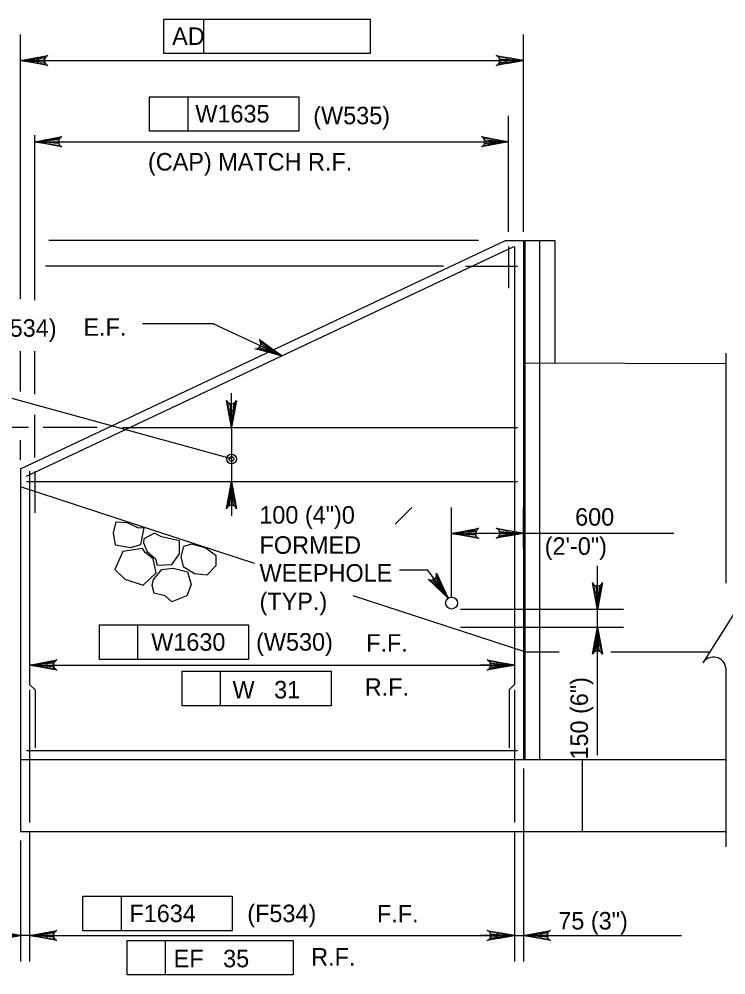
# Model space of a CAD drawing. Extents: x 634540 to 640306, y 296059 to 300275.
# Drawn here: x 639465.1 to 639586.1, y 297349.6 to 297513.4 of the extents above; entities that cross this region are included whole.
import ezdxf

# ---------------------------------------------------------------- set-up
doc = ezdxf.new("R2010")
doc.units = 0
for name, color, linetype in [('10', 7, 'Continuous'), ('3', 7, 'Continuous'), ('4', 7, 'Continuous'), ('5', 7, 'Continuous'), ('6', 7, 'Continuous')]:
    doc.layers.add(name, color=color, linetype=linetype)

# ---------------------------------------------------------------- blocks, each defined once
blk = doc.blocks.new('ROCK')
at = {"layer": '4'}
for points in [[(2.36725, 1.088), (2.2065, 0.82625), (2.378625, 0.506625), (2.66975, 0.3095), (3.128875, 0.403375), (3.48475, 0.6775), (3.4915, 1.123375), (3.25625, 1.36725), (2.783625, 1.308375)], [(1.10175, -0.02725), (1.4015, -0.159125), (1.78825, -0.148875), (1.980875, -0.266), (2.343375, 0.09475), (2.27875, 0.5505), (1.969375, 0.883), (1.4225, 0.553625), (1.152875, 0.479), (1.0105, 0.082)], [(0.74675, 0.359875), (0.882, 0.16), (1.072875, -0.144), (0.892, -0.457375), (0.448125, -0.758625), (0.1, -0.49325), (-0.095, -0.146375), (0.202875, 0.1025), (0.579125, 0.219875)], [(2.231375, -0.71725), (2.2025, -0.266375), (2.45475, 0.037125), (2.9085, 0.28875), (3.2995, 0.047625), (3.46875, -0.344), (3.231625, -0.855), (2.92, -0.860375), (2.5765, -1.054625), (2.340375, -0.904375)], [(1.2085, -0.192875), (0.778375, -0.737625), (1.008375, -1.391375), (1.48725, -1.396875), (2.09825, -1.106625), (2.133375, -0.486375), (1.723125, -0.203375), (1.37425, -0.239875)]]:
    blk.add_lwpolyline(points, close=True, dxfattribs=at)

msp = doc.modelspace()

# ---------------------------------------------------------------- linework, layer by layer
at = {"layer": '10'}
for p, q in [((639465.33, 297436.3), (639548.38, 297475.42)), ((639548.38, 297475.42), (639551.45, 297475.42)), ((639551.45, 297475.42), (639551.45, 297386.47)), ((639551.71, 297475.42), (639556.85, 297475.42)), ((639551.71, 297475.42), (639551.71, 297386.47)), ((639554.18, 297475.42), (639554.18, 297386.47)), ((639556.85, 297475.42), (639556.85, 297454.45)), ((639551.71, 297454.49), (639586.12, 297454.35)), ((639465.33, 297436.3), (639465.33, 297374.16)), ((639505.41, 297420.09), (639465.33, 297433.22)), ((639551.71, 297404.92), (639522.29, 297414.56)), ((639551.71, 297404.92), (639557.55, 297404.92)), ((639566.41, 297404.92), (639583.37, 297404.92)), ((639465.33, 297386.47), (639586.12, 297386.47)), ((639561.51, 297386.47), (639561.51, 297374.16)), ((639465.33, 297374.16), (639586.12, 297374.16))]:
    msp.add_line(p, q, dxfattribs=at)
at = {"layer": '3'}
for p, q in [((639586.12, 297456.16), (639586.12, 297416.69)), ((639590.1, 297415.62), (639582.19, 297403.05)), ((639586.12, 297402.12), (639586.12, 297371.54))]:
    msp.add_line(p, q, dxfattribs=at)
for radius in [0.833, 0.417]:
    msp.add_circle((639501.45, 297438.01), radius, dxfattribs=at)
msp.add_arc((639584, 297401.92), 2.13, 5.3286, 147.8672, dxfattribs=at)
at = {"layer": '4'}
for p, q in [((639489.87, 297513.39), (639525.17, 297513.39)), ((639489.87, 297507.49), (639489.87, 297513.39)), ((639496.71, 297507.49), (639496.71, 297513.39)), ((639525.17, 297513.39), (639525.17, 297507.49)), ((639465.33, 297465.44), (639465.33, 297510.73)), ((639551.45, 297476.96), (639551.45, 297510.73)), ((639525.17, 297507.49), (639489.87, 297507.49)), ((639468.28, 297506.3), (639548.5, 297506.3)), ((639487.42, 297500.1), (639512.96, 297500.1)), ((639487.42, 297494.2), (639487.42, 297500.1)), ((639494.01, 297494.2), (639494.01, 297500.1)), ((639512.96, 297500.1), (639512.96, 297494.2)), ((639548.9, 297476.96), (639548.9, 297496.8)), ((639512.96, 297494.2), (639487.42, 297494.2)), ((639467.75, 297465.24), (639467.75, 297493.53)), ((639467.75, 297492.37), (639548.9, 297492.37)), ((639543.78, 297475.42), (639470.18, 297475.42)), ((639537.78, 297471.06), (639469.61, 297471.06)), ((639498.49, 297461.19), (639486.22, 297461.19)), ((639510.07, 297455.68), (639498.3, 297461.19)), ((639465.33, 297449.58), (639465.33, 297456.47)), ((639467.75, 297449.09), (639467.75, 297456.47)), ((639501.45, 297438.01), (639455.68, 297450.63)), ((639501.45, 297446.33), (639501.45, 297449.28)), ((639467.75, 297438.27), (639467.75, 297445.55)), ((639466.65, 297443.37), (639462.43, 297443.37)), ((639478.46, 297443.37), (639469.16, 297443.37)), ((639501.45, 297443.37), (639501.45, 297434.14)), ((639465.33, 297437.84), (639465.33, 297441.25)), ((639501.45, 297431.19), (639501.45, 297428.24)), ((639529.49, 297426.81), (639532.36, 297429.68)), ((639539.15, 297414.32), (639539.15, 297429.7)), ((639551.45, 297422.73), (639551.45, 297429.7)), ((639542.1, 297425.27), (639577.22, 297425.27)), ((639535.08, 297418.94), (639530.22, 297418.94)), ((639538.55, 297414.13), (639535.08, 297418.94)), ((639564.13, 297387.24), (639564.13, 297419.7)), ((639540.69, 297412.27), (639568.56, 297412.27)), ((639478.81, 297409.55), (639504.35, 297409.55)), ((639478.81, 297403.64), (639478.81, 297409.55)), ((639485.41, 297403.64), (639485.41, 297409.55)), ((639504.35, 297409.55), (639504.35, 297403.64)), ((639540.69, 297409.19), (639568.56, 297409.19)), ((639504.35, 297403.64), (639478.81, 297403.64)), ((639466.87, 297402.68), (639549.91, 297402.68)), ((639469.82, 297402.68), (639472.77, 297402.68)), ((639546.96, 297402.68), (639544.01, 297402.68)), ((639492.97, 297401.61), (639518.51, 297401.61)), ((639492.97, 297395.7), (639492.97, 297401.61)), ((639499.56, 297395.7), (639499.56, 297401.61)), ((639518.51, 297401.61), (639518.51, 297395.7)), ((639518.51, 297395.7), (639492.97, 297395.7)), ((639551.45, 297384.93), (639551.45, 297351.89)), ((639466.87, 297374.16), (639466.87, 297351.89)), ((639549.91, 297374.16), (639549.91, 297351.89)), ((639465.33, 297372.63), (639465.33, 297351.89)), ((639476, 297363.04), (639501.54, 297363.04)), ((639476, 297357.13), (639476, 297363.04)), ((639482.59, 297357.13), (639482.59, 297363.04)), ((639501.54, 297363.04), (639501.54, 297357.13)), ((639466.87, 297356.32), (639465.33, 297356.32)), ((639469.82, 297356.32), (639546.96, 297356.32)), ((639469.82, 297356.32), (639472.77, 297356.32)), ((639469.82, 297356.32), (639537.74, 297356.32)), ((639501.54, 297357.13), (639476, 297357.13)), ((639546.96, 297356.32), (639544.01, 297356.32)), ((639549.91, 297356.32), (639551.45, 297356.32)), ((639554.41, 297356.32), (639557.36, 297356.32)), ((639557.36, 297356.32), (639578.5, 297356.32)), ((639483.58, 297355.47), (639512, 297355.47)), ((639483.58, 297349.57), (639483.58, 297355.47)), ((639490.17, 297349.57), (639490.17, 297355.47)), ((639512, 297355.47), (639512, 297349.57)), ((639512, 297349.57), (639483.58, 297349.57))]:
    msp.add_line(p, q, dxfattribs=at)
for points in [[(639465.33, 297506.3), (639469.99, 297507.17), (639469.63, 297506.92), (639469.44, 297506.61), (639469.39, 297506.3), (639469.44, 297505.98), (639469.63, 297505.67), (639469.99, 297505.42), (639465.33, 297506.3), (639469.63, 297505.67), (639469.44, 297505.98), (639465.33, 297506.3), (639469.39, 297506.3), (639469.44, 297506.61), (639465.33, 297506.3), (639469.63, 297506.92)], [(639551.45, 297506.3), (639546.79, 297505.42), (639547.15, 297505.67), (639547.34, 297505.98), (639547.39, 297506.3), (639547.34, 297506.61), (639547.15, 297506.92), (639546.79, 297507.17), (639551.45, 297506.3), (639547.15, 297506.92), (639547.34, 297506.61), (639551.45, 297506.3), (639547.39, 297506.3), (639547.34, 297505.98), (639551.45, 297506.3), (639547.15, 297505.67)], [(639467.75, 297492.37), (639472.41, 297493.25), (639472.06, 297493), (639471.87, 297492.68), (639471.82, 297492.37), (639471.87, 297492.06), (639472.06, 297491.75), (639472.41, 297491.5), (639467.75, 297492.37), (639472.06, 297491.75), (639471.87, 297492.06), (639467.75, 297492.37), (639471.82, 297492.37), (639471.87, 297492.68), (639467.75, 297492.37), (639472.06, 297493)], [(639548.9, 297492.37), (639544.24, 297491.5), (639544.6, 297491.75), (639544.79, 297492.06), (639544.84, 297492.37), (639544.79, 297492.68), (639544.6, 297493), (639544.24, 297493.25), (639548.9, 297492.37), (639544.6, 297493), (639544.79, 297492.68), (639548.9, 297492.37), (639544.84, 297492.37), (639544.79, 297492.06), (639548.9, 297492.37), (639544.6, 297491.75)], [(639510.07, 297455.68), (639505.48, 297456.86), (639505.91, 297456.94), (639506.21, 297457.14), (639506.39, 297457.4), (639506.47, 297457.71), (639506.44, 297458.07), (639506.22, 297458.45), (639510.07, 297455.68), (639506.44, 297458.07), (639506.47, 297457.71), (639510.07, 297455.68), (639506.39, 297457.4), (639506.21, 297457.14), (639510.07, 297455.68), (639505.91, 297456.94)], [(639501.45, 297443.37), (639500.58, 297448.03), (639500.83, 297447.67), (639501.14, 297447.49), (639501.45, 297447.43), (639501.77, 297447.49), (639502.08, 297447.67), (639502.33, 297448.03), (639501.45, 297443.37), (639502.08, 297447.67), (639501.77, 297447.49), (639501.45, 297443.37), (639501.45, 297447.43), (639501.14, 297447.49), (639501.45, 297443.37), (639500.83, 297447.67)], [(639501.45, 297434.14), (639502.33, 297429.48), (639502.08, 297429.84), (639501.77, 297430.03), (639501.45, 297430.08), (639501.14, 297430.03), (639500.83, 297429.84), (639500.58, 297429.48), (639501.45, 297434.14), (639500.83, 297429.84), (639501.14, 297430.03), (639501.45, 297434.14), (639501.45, 297430.08), (639501.77, 297430.03), (639501.45, 297434.14), (639502.08, 297429.84)], [(639539.15, 297425.24), (639543.81, 297426.12), (639543.45, 297425.87), (639543.27, 297425.56), (639543.21, 297425.24), (639543.27, 297424.93), (639543.45, 297424.62), (639543.81, 297424.37), (639539.15, 297425.24), (639543.45, 297424.62), (639543.27, 297424.93), (639539.15, 297425.24), (639543.21, 297425.24), (639543.27, 297425.56), (639539.15, 297425.24), (639543.45, 297425.87)], [(639551.45, 297425.27), (639546.79, 297424.4), (639547.15, 297424.65), (639547.34, 297424.96), (639547.39, 297425.27), (639547.34, 297425.58), (639547.15, 297425.9), (639546.79, 297426.14), (639551.45, 297425.27), (639547.15, 297425.9), (639547.34, 297425.58), (639551.45, 297425.27), (639547.39, 297425.27), (639547.34, 297424.96), (639551.45, 297425.27), (639547.15, 297424.65)], [(639538.55, 297414.13), (639535.11, 297417.4), (639535.52, 297417.25), (639535.89, 297417.29), (639536.17, 297417.43), (639536.39, 297417.65), (639536.54, 297417.98), (639536.53, 297418.42), (639538.55, 297414.13), (639536.54, 297417.98), (639536.39, 297417.65), (639538.55, 297414.13), (639536.17, 297417.43), (639535.89, 297417.29), (639538.55, 297414.13), (639535.52, 297417.25)], [(639564.13, 297412.15), (639563.26, 297416.81), (639563.51, 297416.45), (639563.82, 297416.27), (639564.13, 297416.21), (639564.44, 297416.27), (639564.76, 297416.45), (639565.01, 297416.81), (639564.13, 297412.15), (639564.76, 297416.45), (639564.44, 297416.27), (639564.13, 297412.15), (639564.13, 297416.21), (639563.82, 297416.27), (639564.13, 297412.15), (639563.51, 297416.45)], [(639564.13, 297409.19), (639565.01, 297404.53), (639564.76, 297404.88), (639564.44, 297405.07), (639564.13, 297405.12), (639563.82, 297405.07), (639563.51, 297404.88), (639563.26, 297404.53), (639564.13, 297409.19), (639563.51, 297404.88), (639563.82, 297405.07), (639564.13, 297409.19), (639564.13, 297405.12), (639564.44, 297405.07), (639564.13, 297409.19), (639564.76, 297404.88)], [(639466.87, 297402.68), (639471.53, 297403.55), (639471.17, 297403.31), (639470.98, 297402.99), (639470.93, 297402.68), (639470.98, 297402.37), (639471.17, 297402.06), (639471.53, 297401.81), (639466.87, 297402.68), (639471.17, 297402.06), (639470.98, 297402.37), (639466.87, 297402.68), (639470.93, 297402.68), (639470.98, 297402.99), (639466.87, 297402.68), (639471.17, 297403.31)], [(639549.91, 297402.68), (639545.25, 297401.81), (639545.61, 297402.06), (639545.8, 297402.37), (639545.85, 297402.68), (639545.8, 297402.99), (639545.61, 297403.31), (639545.25, 297403.55), (639549.91, 297402.68), (639545.61, 297403.31), (639545.8, 297402.99), (639549.91, 297402.68), (639545.85, 297402.68), (639545.8, 297402.37), (639549.91, 297402.68), (639545.61, 297402.06)], [(639465.33, 297356.32), (639460.67, 297355.45), (639461.03, 297355.7), (639461.21, 297356.01), (639461.27, 297356.32), (639461.21, 297356.63), (639461.03, 297356.95), (639460.67, 297357.19), (639465.33, 297356.32), (639461.03, 297356.95), (639461.21, 297356.63), (639465.33, 297356.32), (639461.27, 297356.32), (639461.21, 297356.01), (639465.33, 297356.32), (639461.03, 297355.7)], [(639466.87, 297356.32), (639471.53, 297357.19), (639471.17, 297356.95), (639470.98, 297356.63), (639470.93, 297356.32), (639470.98, 297356.01), (639471.17, 297355.7), (639471.53, 297355.45), (639466.87, 297356.32), (639471.17, 297355.7), (639470.98, 297356.01), (639466.87, 297356.32), (639470.93, 297356.32), (639470.98, 297356.63), (639466.87, 297356.32), (639471.17, 297356.95)], [(639549.91, 297356.32), (639545.25, 297355.45), (639545.61, 297355.7), (639545.8, 297356.01), (639545.85, 297356.32), (639545.8, 297356.63), (639545.61, 297356.95), (639545.25, 297357.19), (639549.91, 297356.32), (639545.61, 297356.95), (639545.8, 297356.63), (639549.91, 297356.32), (639545.85, 297356.32), (639545.8, 297356.01), (639549.91, 297356.32), (639545.61, 297355.7)], [(639551.45, 297356.32), (639556.11, 297357.19), (639555.75, 297356.95), (639555.57, 297356.63), (639555.52, 297356.32), (639555.57, 297356.01), (639555.75, 297355.7), (639556.11, 297355.45), (639551.45, 297356.32), (639555.75, 297355.7), (639555.57, 297356.01), (639551.45, 297356.32), (639555.52, 297356.32), (639555.57, 297356.63), (639551.45, 297356.32), (639555.75, 297356.95)]]:
    msp.add_lwpolyline(points, dxfattribs=at)
for points in [[(639468.28, 297506.79), (639468.28, 297505.8), (639465.33, 297506.3)], [(639548.5, 297506.79), (639548.5, 297505.8), (639551.45, 297506.3)], [(639507.6, 297457.37), (639507.19, 297456.48), (639510.07, 297455.68)], [(639500.96, 297446.33), (639501.95, 297446.33), (639501.45, 297443.37)], [(639500.96, 297431.19), (639501.95, 297431.19), (639501.45, 297434.14)], [(639542.1, 297425.76), (639542.1, 297424.78), (639539.15, 297425.27)], [(639548.5, 297425.76), (639548.5, 297424.78), (639551.45, 297425.27)], [(639563.64, 297415.1), (639564.63, 297415.1), (639564.13, 297412.15)], [(639563.64, 297405.97), (639564.63, 297405.97), (639564.13, 297408.92)], [(639469.82, 297403.17), (639469.82, 297402.19), (639466.87, 297402.68)], [(639546.96, 297403.17), (639546.96, 297402.19), (639549.91, 297402.68)], [(639462.37, 297356.81), (639462.37, 297355.83), (639465.33, 297356.32)], [(639469.82, 297356.81), (639469.82, 297355.83), (639466.87, 297356.32)], [(639546.96, 297356.81), (639546.96, 297355.83), (639549.91, 297356.32)], [(639554.41, 297356.81), (639554.41, 297355.83), (639551.45, 297356.32)]]:
    msp.add_lwpolyline(points, close=True, dxfattribs=at)
msp.add_circle((639539.15, 297413.3), 1.03, dxfattribs=at)
at = {"layer": '5'}
for p, q in [((639548.89, 297474.4), (639548.9, 297467.3)), ((639467.75, 297435.89), (639467.76, 297428.79))]:
    msp.add_line(p, q, dxfattribs=at)
at = {"layer": '6'}
for p, q in [((639466.35, 297435.08), (639549.81, 297474.4)), ((639549.91, 297474.4), (639549.91, 297399.34)), ((639541.51, 297471.06), (639550.43, 297471.06)), ((639482.75, 297443.37), (639550.43, 297443.37)), ((639466.87, 297435.89), (639466.87, 297399.34)), ((639466.35, 297434.14), (639550.43, 297434.14)), ((639466.87, 297399.34), (639467.8, 297398.41)), ((639549.91, 297399.34), (639548.98, 297398.41)), ((639466.87, 297398.41), (639466.87, 297375.7)), ((639467.8, 297398.41), (639467.8, 297388.47)), ((639548.98, 297398.41), (639548.98, 297388.47)), ((639549.91, 297398.41), (639549.91, 297375.7)), ((639466.35, 297388.01), (639550.43, 297388.01))]:
    msp.add_line(p, q, dxfattribs=at)

# ---------------------------------------------------------------- block references
at = {"layer": '4', "xscale": 4.921475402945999, "yscale": 4.921475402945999, "rotation": -43.131989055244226}
msp.add_blockref('ROCK', (639482.51, 297427.43), dxfattribs=at)

# ---------------------------------------------------------------- texts
at = {"layer": '3'}
msp.add_text('100 (4")0', height=3, dxfattribs=at).set_placement((639506.21, 297426.92))
at = {"layer": '4'}
for s, height, p in [('AD', 3, (639491.28, 297508.97)), ('W1635', 3, (639495.25, 297495.68)), ('(W535)', 3, (639515.45, 297495.37)), ('(CAP) MATCH R.F.', 3.0001, (639487.14, 297487.44)), ('(W534)', 3, (639458.33, 297458.95)), ('E.F.', 3, (639476.08, 297459.11)), ('600', 3, (639560.3, 297426.57)), ('FORMED', 3, (639506.25, 297421.75)), ('(2\'-0")', 3, (639555.09, 297421.57)), ('WEEPHOLE', 3, (639506.25, 297416.97)), ('(TYP.)', 3, (639506.25, 297412.09)), ('W1630', 3, (639487.69, 297405.13)), ('(W530)', 3, (639505.66, 297405.15)), ('F.F.', 3, (639524.52, 297404.96)), ('R.F.', 3, (639524.27, 297397.41)), ('W   31', 3, (639501.62, 297396.96)), ('F1634', 3, (639483.96, 297358.61)), ('(F534)', 3, (639504.15, 297358.61)), ('F.F.', 3, (639526.36, 297358.55)), ('75 (3")', 3, (639557.42, 297357.35)), ('EF   35', 3, (639491.54, 297350.87)), ('R.F.', 3, (639515.09, 297351.16))]:
    msp.add_text(s, height=height, dxfattribs=at).set_placement(p)
msp.add_text('150 (6")', height=3, rotation=90, dxfattribs=at).set_placement((639562.5, 297386.48))

doc.saveas('drawing.dxf')
